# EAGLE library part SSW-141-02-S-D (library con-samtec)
THROUGH-HOLE .025" SQ POST SOCKET Source: Samtec SSW.pdf
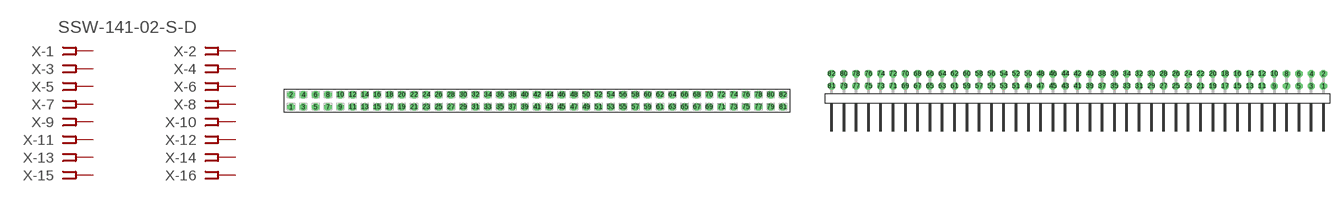
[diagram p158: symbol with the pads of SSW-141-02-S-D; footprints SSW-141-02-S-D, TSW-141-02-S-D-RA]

Designator prefix X; gates -1=FPINV -2=FPIN -3=FPIN -4=FPIN -5=FPIN -6=FPIN -7=FPIN -8=FPIN -9=FPIN -10=FPIN -11=FPIN -12=FPIN -13=FPIN -14=FPIN -15=FPIN -16=FPIN -17=FPIN -18=FPIN -19=FPIN -20=FPIN -21=FPIN -22=FPIN -23=FPIN -24=FPIN -25=FPIN -26=FPIN -27=FPIN -28=FPIN -29=FPIN -30=FPIN -31=FPIN -32=FPIN -33=FPIN -34=FPIN -35=FPIN -36=FPIN -37=FPIN -38=FPIN -39=FPIN -40=FPIN -41=FPIN -42=FPIN -43=FPIN -44=FPIN -45=FPIN -46=FPIN -47=FPIN -48=FPIN -49=FPIN -50=FPIN -51=FPIN -52=FPIN -53=FPIN -54=FPIN -55=FPIN -56=FPIN -57=FPIN -58=FPIN -59=FPIN -60=FPIN -61=FPIN -62=FPIN -63=FPIN -64=FPIN -65=FPIN -66=FPIN -67=FPIN -68=FPIN -69=FPIN -70=FPIN -71=FPIN -72=FPIN -73=FPIN -74=FPIN -75=FPIN -76=FPIN -77=FPIN -78=FPIN -79=FPIN -80=FPIN -81=FPIN -82=FPIN

## SSW-141-02-S-D (OC_FARNELL: unknown; OC_NEWARK: unknown)  [SSW-141-02-S-D]
1  -1:1  pas
2  -2:1  pas
3  -3:1  pas
4  -4:1  pas
5  -5:1  pas
6  -6:1  pas
7  -7:1  pas
8  -8:1  pas
9  -9:1  pas
10  -10:1  pas
11  -11:1  pas
12  -12:1  pas
13  -13:1  pas
14  -14:1  pas
15  -15:1  pas
16  -16:1  pas
17  -17:1  pas
18  -18:1  pas
19  -19:1  pas
20  -20:1  pas
21  -21:1  pas
22  -22:1  pas
23  -23:1  pas
24  -24:1  pas
25  -25:1  pas
26  -26:1  pas
27  -27:1  pas
28  -28:1  pas
29  -29:1  pas
30  -30:1  pas
31  -31:1  pas
32  -32:1  pas
33  -33:1  pas
34  -34:1  pas
35  -35:1  pas
36  -36:1  pas
37  -37:1  pas
38  -38:1  pas
39  -39:1  pas
40  -40:1  pas
41  -41:1  pas
42  -42:1  pas
43  -43:1  pas
44  -44:1  pas
45  -45:1  pas
46  -46:1  pas
47  -47:1  pas
48  -48:1  pas
49  -49:1  pas
50  -50:1  pas
51  -51:1  pas
52  -52:1  pas
53  -53:1  pas
54  -54:1  pas
55  -55:1  pas
56  -56:1  pas
57  -57:1  pas
58  -58:1  pas
59  -59:1  pas
60  -60:1  pas
61  -61:1  pas
62  -62:1  pas
63  -63:1  pas
64  -64:1  pas
65  -65:1  pas
66  -66:1  pas
67  -67:1  pas
68  -68:1  pas
69  -69:1  pas
70  -70:1  pas
71  -71:1  pas
72  -72:1  pas
73  -73:1  pas
74  -74:1  pas
75  -75:1  pas
76  -76:1  pas
77  -77:1  pas
78  -78:1  pas
79  -79:1  pas
80  -80:1  pas
81  -81:1  pas
82  -82:1  pas

## SSW-141-02-S-D-RA (OC_FARNELL: unknown; OC_NEWARK: unknown)  [TSW-141-02-S-D-RA]
Pads as for SSW-141-02-S-D

## Footprint SSW-141-02-S-D (pad centres in mm)
THROUGH-HOLE .025" SQ POST SOCKET Source: Samtec SSW.pdf
drill 1 pad 1.5 octagon: 1 -50.8,-1.27; 2 -50.8,1.27; 3 -48.26,-1.27; 4 -48.26,1.27; 5 -45.72,-1.27; 6 -45.72,1.27; 7 -43.18,-1.27; 8 -43.18,1.27; 9 -40.64,-1.27; 10 -40.64,1.27; 11 -38.1,-1.27; 12 -38.1,1.27; 13 -35.56,-1.27; 14 -35.56,1.27; 15 -33.02,-1.27; 16 -33.02,1.27; 17 -30.48,-1.27; 18 -30.48,1.27; 19 -27.94,-1.27; 20 -27.94,1.27; 21 -25.4,-1.27; 22 -25.4,1.27; 23 -22.86,-1.27; 24 -22.86,1.27; 25 -20.32,-1.27; 26 -20.32,1.27; 27 -17.78,-1.27; 28 -17.78,1.27; 29 -15.24,-1.27; 30 -15.24,1.27; 31 -12.7,-1.27; 32 -12.7,1.27; 33 -10.16,-1.27; 34 -10.16,1.27; 35 -7.62,-1.27; 36 -7.62,1.27; 37 -5.08,-1.27; 38 -5.08,1.27; 39 -2.54,-1.27; 40 -2.54,1.27; 41 0,-1.27; 42 0,1.27; 43 2.54,-1.27; 44 2.54,1.27; 45 5.08,-1.27; 46 5.08,1.27; 47 7.62,-1.27; 48 7.62,1.27; 49 10.16,-1.27; 50 10.16,1.27; 51 12.7,-1.27; 52 12.7,1.27; 53 15.24,-1.27; 54 15.24,1.27; 55 17.78,-1.27; 56 17.78,1.27; 57 20.32,-1.27; 58 20.32,1.27; 59 22.86,-1.27; 60 22.86,1.27; 61 25.4,-1.27; 62 25.4,1.27; 63 27.94,-1.27; 64 27.94,1.27; 65 30.48,-1.27; 66 30.48,1.27; 67 33.02,-1.27; 68 33.02,1.27; 69 35.56,-1.27; 70 35.56,1.27; 71 38.1,-1.27; 72 38.1,1.27; 73 40.64,-1.27; 74 40.64,1.27; 75 43.18,-1.27; 76 43.18,1.27; 77 45.72,-1.27; 78 45.72,1.27; 79 48.26,-1.27; 80 48.26,1.27; 81 50.8,-1.27; 82 50.8,1.27

## Footprint TSW-141-02-S-D-RA (pad centres in mm)
THROUGH-HOLE .025" SQ POST HEADER Source: Samtec TSW.pdf
drill 1 pad 1.5 octagon: 1 50.8,1.524; 2 50.8,4.064; 3 48.26,1.524; 4 48.26,4.064; 5 45.72,1.524; 6 45.72,4.064; 7 43.18,1.524; 8 43.18,4.064; 9 40.64,1.524; 10 40.64,4.064; 11 38.1,1.524; 12 38.1,4.064; 13 35.56,1.524; 14 35.56,4.064; 15 33.02,1.524; 16 33.02,4.064; 17 30.48,1.524; 18 30.48,4.064; 19 27.94,1.524; 20 27.94,4.064; 21 25.4,1.524; 22 25.4,4.064; 23 22.86,1.524; 24 22.86,4.064; 25 20.32,1.524; 26 20.32,4.064; 27 17.78,1.524; 28 17.78,4.064; 29 15.24,1.524; 30 15.24,4.064; 31 12.7,1.524; 32 12.7,4.064; 33 10.16,1.524; 34 10.16,4.064; 35 7.62,1.524; 36 7.62,4.064; 37 5.08,1.524; 38 5.08,4.064; 39 2.54,1.524; 40 2.54,4.064; 41 0,1.524; 42 0,4.064; 43 -2.54,1.524; 44 -2.54,4.064; 45 -5.08,1.524; 46 -5.08,4.064; 47 -7.62,1.524; 48 -7.62,4.064; 49 -10.16,1.524; 50 -10.16,4.064; 51 -12.7,1.524; 52 -12.7,4.064; 53 -15.24,1.524; 54 -15.24,4.064; 55 -17.78,1.524; 56 -17.78,4.064; 57 -20.32,1.524; 58 -20.32,4.064; 59 -22.86,1.524; 60 -22.86,4.064; 61 -25.4,1.524; 62 -25.4,4.064; 63 -27.94,1.524; 64 -27.94,4.064; 65 -30.48,1.524; 66 -30.48,4.064; 67 -33.02,1.524; 68 -33.02,4.064; 69 -35.56,1.524; 70 -35.56,4.064; 71 -38.1,1.524; 72 -38.1,4.064; 73 -40.64,1.524; 74 -40.64,4.064; 75 -43.18,1.524; 76 -43.18,4.064; 77 -45.72,1.524; 78 -45.72,4.064; 79 -48.26,1.524; 80 -48.26,4.064; 81 -50.8,1.524; 82 -50.8,4.064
